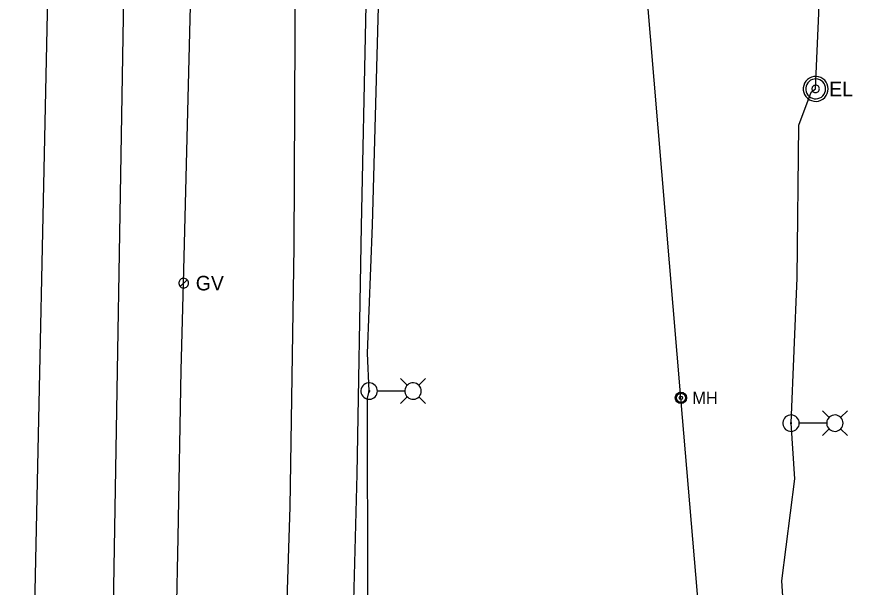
# Model space of a CAD drawing. Extents: x 600849 to 606371, y 330010 to 403088.
# Drawn here: x 604803.1 to 605024.2, y 333261.8 to 333412.8 of the extents above; entities that cross this region are included whole.
import ezdxf

# ---------------------------------------------------------------- set-up
doc = ezdxf.new("R2010")
doc.units = 0
for name, color, linetype in [('E_FTMS_Conduit', 7, 'Continuous'), ('E_LTG', 7, 'Continuous'), ('E_LTG_CID', 7, 'Continuous'), ('E_UTL_E', 7, 'Continuous'), ('E_UTL_E_UG', 7, 'Continuous'), ('E_UTL_G', 7, 'Continuous'), ('E_UTL_G_UG', 7, 'Continuous'), ('E_UTL_SAN_UG', 7, 'Continuous'), ('E_UTL_SAN_UG_MMSD', 7, 'Continuous'), ('E_UTL_W_UG', 7, 'Continuous')]:
    doc.layers.add(name, color=color, linetype=linetype)

msp = doc.modelspace()

# ---------------------------------------------------------------- linework, layer by layer
at = {"layer": 'E_FTMS_Conduit'}
msp.add_lwpolyline([(604834.27, 332793.51), (604834.27, 332793.51), (604837.8, 332828.79), (604843.62, 332859.54), (604848.45, 332908.55), (604857.59, 332953.99), (604870.57, 332999.81), (604881.56, 333070.85), (604883.3, 333104.02), (604886.34, 333150.08), (604892.01, 333248.16), (604893.18, 333291.76), (604894.37, 333357.39), (604896.64, 333466.11)], dxfattribs=at)
at = {"layer": 'E_LTG'}
for points in [[(604898.55, 333313.71), (604898.51, 333314.13), (604898.39, 333314.52), (604898.2, 333314.89), (604897.94, 333315.21), (604897.63, 333315.49), (604897.27, 333315.69), (604896.88, 333315.83), (604896.47, 333315.89), (604896.06, 333315.87), (604895.66, 333315.77), (604895.28, 333315.6), (604894.95, 333315.36), (604894.66, 333315.06), (604894.44, 333314.71), (604894.28, 333314.33), (604894.2, 333313.92), (604894.2, 333313.51), (604894.28, 333313.1), (604894.44, 333312.72), (604894.66, 333312.37), (604894.95, 333312.07), (604895.28, 333311.83), (604895.66, 333311.66), (604896.06, 333311.56), (604896.47, 333311.54), (604896.88, 333311.6), (604897.27, 333311.73), (604897.63, 333311.94), (604897.94, 333312.21), (604898.2, 333312.54), (604898.39, 333312.9), (604898.51, 333313.3), (604898.55, 333313.71)], [(604906.45, 333315.24), (604904.67, 333317.01)], [(604910.15, 333313.71), (604910.11, 333314.13), (604909.99, 333314.52), (604909.8, 333314.89), (604909.55, 333315.21), (604909.24, 333315.49), (604908.88, 333315.69), (604908.49, 333315.83), (604908.08, 333315.89), (604907.66, 333315.87), (604907.26, 333315.77), (604906.89, 333315.6), (604906.55, 333315.36), (604906.26, 333315.06), (604906.04, 333314.71), (604905.89, 333314.33), (604905.81, 333313.92), (604905.81, 333313.51), (604905.89, 333313.1), (604906.04, 333312.72), (604906.26, 333312.37), (604906.55, 333312.07), (604906.89, 333311.83), (604907.26, 333311.66), (604907.66, 333311.56), (604908.08, 333311.54), (604908.49, 333311.6), (604908.88, 333311.73), (604909.24, 333311.94), (604909.55, 333312.21), (604909.8, 333312.54), (604909.99, 333312.9), (604910.11, 333313.3), (604910.15, 333313.71)], [(604909.5, 333315.24), (604911.27, 333317.01)], [(604896.54, 333313.71), (604896.53, 333313.74), (604896.52, 333313.78), (604896.51, 333313.8), (604896.49, 333313.83), (604896.47, 333313.85), (604896.44, 333313.86), (604896.41, 333313.88), (604896.38, 333313.88), (604896.35, 333313.88), (604896.32, 333313.87), (604896.29, 333313.86), (604896.26, 333313.84), (604896.24, 333313.82), (604896.22, 333313.79), (604896.21, 333313.76), (604896.2, 333313.73), (604896.2, 333313.7), (604896.21, 333313.67), (604896.22, 333313.64), (604896.24, 333313.61), (604896.26, 333313.59), (604896.29, 333313.57), (604896.32, 333313.56), (604896.35, 333313.55), (604896.38, 333313.55), (604896.41, 333313.55), (604896.44, 333313.56), (604896.47, 333313.58), (604896.49, 333313.6), (604896.51, 333313.62), (604896.52, 333313.65), (604896.53, 333313.68), (604896.54, 333313.71)], [(604905.76, 333313.71), (604898.58, 333313.71)], [(604906.45, 333312.19), (604904.67, 333310.41)], [(604909.5, 333312.19), (604911.27, 333310.41)], [(605010.13, 333305.22), (605010.09, 333305.63), (605009.98, 333306.03), (605009.79, 333306.4), (605009.53, 333306.72), (605009.22, 333306.99), (605008.86, 333307.2), (605008.47, 333307.33), (605008.06, 333307.39), (605007.65, 333307.37), (605007.24, 333307.28), (605006.87, 333307.1), (605006.53, 333306.86), (605006.25, 333306.57), (605006.02, 333306.22), (605005.87, 333305.83), (605005.79, 333305.43), (605005.79, 333305.01), (605005.87, 333304.61), (605006.02, 333304.22), (605006.25, 333303.88), (605006.53, 333303.58), (605006.87, 333303.34), (605007.24, 333303.16), (605007.65, 333303.07), (605008.06, 333303.05), (605008.47, 333303.11), (605008.86, 333303.24), (605009.22, 333303.45), (605009.53, 333303.72), (605009.79, 333304.04), (605009.98, 333304.41), (605010.09, 333304.81), (605010.13, 333305.22)], [(605018.04, 333306.75), (605016.26, 333308.52)], [(605021.73, 333305.22), (605021.7, 333305.63), (605021.58, 333306.03), (605021.39, 333306.4), (605021.13, 333306.72), (605020.82, 333306.99), (605020.46, 333307.2), (605020.07, 333307.33), (605019.66, 333307.39), (605019.25, 333307.37), (605018.85, 333307.28), (605018.47, 333307.1), (605018.13, 333306.86), (605017.85, 333306.57), (605017.63, 333306.22), (605017.47, 333305.83), (605017.39, 333305.43), (605017.39, 333305.01), (605017.47, 333304.61), (605017.63, 333304.22), (605017.85, 333303.88), (605018.13, 333303.58), (605018.47, 333303.34), (605018.85, 333303.16), (605019.25, 333303.07), (605019.66, 333303.05), (605020.07, 333303.11), (605020.46, 333303.24), (605020.82, 333303.45), (605021.13, 333303.72), (605021.39, 333304.04), (605021.58, 333304.41), (605021.7, 333304.81), (605021.73, 333305.22)], [(605021.08, 333306.75), (605022.86, 333308.52)], [(605008.12, 333305.22), (605008.12, 333305.25), (605008.11, 333305.28), (605008.1, 333305.31), (605008.08, 333305.34), (605008.05, 333305.36), (605008.03, 333305.37), (605008, 333305.38), (605007.96, 333305.39), (605007.93, 333305.39), (605007.9, 333305.38), (605007.87, 333305.36), (605007.85, 333305.35), (605007.83, 333305.32), (605007.81, 333305.3), (605007.8, 333305.27), (605007.79, 333305.24), (605007.79, 333305.2), (605007.8, 333305.17), (605007.81, 333305.14), (605007.83, 333305.12), (605007.85, 333305.09), (605007.87, 333305.08), (605007.9, 333305.06), (605007.93, 333305.06), (605007.96, 333305.05), (605008, 333305.06), (605008.03, 333305.07), (605008.05, 333305.08), (605008.08, 333305.11), (605008.1, 333305.13), (605008.11, 333305.16), (605008.12, 333305.19), (605008.12, 333305.22)], [(605017.35, 333305.22), (605010.17, 333305.22)], [(605018.04, 333303.7), (605016.26, 333301.92)], [(605021.08, 333303.7), (605022.86, 333301.92)]]:
    msp.add_lwpolyline(points, dxfattribs=at)
at = {"layer": 'E_LTG_CID'}
for points in [[(605014.47, 333393.69), (605015.31, 333413.75), (605015.88, 333465.08), (605016.33, 333493.73), (605016.6, 333495.89), (605016.64, 333498.09), (605017.72, 333545.18), (605018.86, 333593.18), (605019.31, 333619.04), (605019.11, 333662.74), (605017.7, 333668.32), (605017.29, 333684.65), (605016.2, 333704.19), (605012.52, 333714.35), (605010.86, 333742.99), (605009.02, 333796.81), (605006.86, 333832.68), (605008.56, 333838.78), (605005.64, 333851.75), (605010.35, 333891.22), (605002.22, 333986.67)], [(604879.6, 332255.02), (604881.21, 332520.43), (604882.73, 332780.27), (604878.2, 332790.52), (604877.91, 332791.78), (604881.34, 332802.26), (604883.13, 332854.03), (604882.52, 332888.97), (604884.51, 332915.54), (604885.08, 332965.87), (604885.55, 333001.94), (604887.55, 333053.11), (604887.38, 333057.43), (604890.09, 333114.03), (604893.58, 333149.05), (604892.31, 333167.75), (604894.55, 333225.52), (604896.01, 333258.34), (604895.95, 333311.87), (604895.91, 333311.87), (604896.37, 333313.71), (604895.92, 333323.72), (604897.23, 333357.63), (604900.28, 333466.82)], [(605007.96, 333305.22), (605009.56, 333343.65), (605010.05, 333384.12), (605013.28, 333392.8), (605014.47, 333393.69)], [(605004.43, 333142.5), (605005.3, 333147), (605005.59, 333179.13), (605007.26, 333236.01), (605005.55, 333263.51), (605008.97, 333290.48), (605007.96, 333305.22)]]:
    msp.add_lwpolyline(points, dxfattribs=at)
at = {"layer": 'E_UTL_E'}
for points in [[(605017.77, 333393.69), (605017.71, 333394.32), (605017.54, 333394.92), (605017.25, 333395.48), (605016.86, 333395.97), (605016.39, 333396.38), (605015.84, 333396.7), (605015.25, 333396.9), (605014.63, 333396.99), (605014, 333396.96), (605013.39, 333396.81), (605012.82, 333396.55), (605012.31, 333396.19), (605011.88, 333395.73), (605011.54, 333395.21), (605011.31, 333394.62), (605011.19, 333394.01), (605011.19, 333393.38), (605011.31, 333392.76), (605011.54, 333392.18), (605011.88, 333391.65), (605012.31, 333391.2), (605012.82, 333390.84), (605013.39, 333390.58), (605014, 333390.43), (605014.63, 333390.4), (605015.25, 333390.49), (605015.84, 333390.69), (605016.39, 333391.01), (605016.86, 333391.42), (605017.25, 333391.91), (605017.54, 333392.47), (605017.71, 333393.07), (605017.77, 333393.69)], [(605017.77, 333393.69), (605017.71, 333394.32), (605017.54, 333394.92), (605017.25, 333395.48), (605016.86, 333395.97), (605016.39, 333396.38), (605015.84, 333396.7), (605015.25, 333396.9), (605014.63, 333396.99), (605014, 333396.96), (605013.39, 333396.81), (605012.82, 333396.55), (605012.31, 333396.19), (605011.88, 333395.73), (605011.54, 333395.21), (605011.31, 333394.62), (605011.19, 333394.01), (605011.19, 333393.38), (605011.31, 333392.76), (605011.54, 333392.18), (605011.88, 333391.65), (605012.31, 333391.2), (605012.82, 333390.84), (605013.39, 333390.58), (605014, 333390.43), (605014.63, 333390.4), (605015.25, 333390.49), (605015.84, 333390.69), (605016.39, 333391.01), (605016.86, 333391.42), (605017.25, 333391.91), (605017.54, 333392.47), (605017.71, 333393.07), (605017.77, 333393.69)], [(605017.11, 333393.69), (605017.06, 333394.19), (605016.92, 333394.68), (605016.69, 333395.12), (605016.38, 333395.52), (605016, 333395.84), (605015.57, 333396.1), (605015.09, 333396.26), (605014.6, 333396.33), (605014.1, 333396.31), (605013.61, 333396.19), (605013.15, 333395.98), (605012.74, 333395.69), (605012.4, 333395.33), (605012.13, 333394.9), (605011.94, 333394.44), (605011.84, 333393.95), (605011.84, 333393.44), (605011.94, 333392.95), (605012.13, 333392.48), (605012.4, 333392.06), (605012.74, 333391.7), (605013.15, 333391.41), (605013.61, 333391.2), (605014.1, 333391.08), (605014.6, 333391.06), (605015.09, 333391.13), (605015.57, 333391.29), (605016, 333391.54), (605016.38, 333391.87), (605016.69, 333392.27), (605016.92, 333392.71), (605017.06, 333393.19), (605017.11, 333393.69)], [(605017.11, 333393.69), (605017.06, 333394.19), (605016.92, 333394.68), (605016.69, 333395.12), (605016.38, 333395.52), (605016, 333395.84), (605015.57, 333396.1), (605015.09, 333396.26), (605014.6, 333396.33), (605014.1, 333396.31), (605013.61, 333396.19), (605013.15, 333395.98), (605012.74, 333395.69), (605012.4, 333395.33), (605012.13, 333394.9), (605011.94, 333394.44), (605011.84, 333393.95), (605011.84, 333393.44), (605011.94, 333392.95), (605012.13, 333392.48), (605012.4, 333392.06), (605012.74, 333391.7), (605013.15, 333391.41), (605013.61, 333391.2), (605014.1, 333391.08), (605014.6, 333391.06), (605015.09, 333391.13), (605015.57, 333391.29), (605016, 333391.54), (605016.38, 333391.87), (605016.69, 333392.27), (605016.92, 333392.71), (605017.06, 333393.19), (605017.11, 333393.69)], [(605015.46, 333393.69), (605015.44, 333393.88), (605015.39, 333394.06), (605015.3, 333394.23), (605015.19, 333394.38), (605015.05, 333394.5), (605014.88, 333394.59), (605014.71, 333394.66), (605014.52, 333394.68), (605014.33, 333394.67), (605014.15, 333394.63), (605013.98, 333394.55), (605013.82, 333394.44), (605013.69, 333394.31), (605013.59, 333394.15), (605013.52, 333393.97), (605013.49, 333393.79), (605013.49, 333393.6), (605013.52, 333393.42), (605013.59, 333393.24), (605013.69, 333393.08), (605013.82, 333392.95), (605013.98, 333392.84), (605014.15, 333392.76), (605014.33, 333392.71), (605014.52, 333392.71), (605014.71, 333392.73), (605014.88, 333392.79), (605015.05, 333392.89), (605015.19, 333393.01), (605015.3, 333393.16), (605015.39, 333393.33), (605015.44, 333393.51), (605015.46, 333393.69)], [(605015.46, 333393.69), (605015.44, 333393.88), (605015.39, 333394.06), (605015.3, 333394.23), (605015.19, 333394.38), (605015.05, 333394.5), (605014.88, 333394.59), (605014.71, 333394.66), (605014.52, 333394.68), (605014.33, 333394.67), (605014.15, 333394.63), (605013.98, 333394.55), (605013.82, 333394.44), (605013.69, 333394.31), (605013.59, 333394.15), (605013.52, 333393.97), (605013.49, 333393.79), (605013.49, 333393.6), (605013.52, 333393.42), (605013.59, 333393.24), (605013.69, 333393.08), (605013.82, 333392.95), (605013.98, 333392.84), (605014.15, 333392.76), (605014.33, 333392.71), (605014.52, 333392.71), (605014.71, 333392.73), (605014.88, 333392.79), (605015.05, 333392.89), (605015.19, 333393.01), (605015.3, 333393.16), (605015.39, 333393.33), (605015.44, 333393.51), (605015.46, 333393.69)]]:
    msp.add_lwpolyline(points, dxfattribs=at)
at = {"layer": 'E_UTL_E_UG'}
msp.add_lwpolyline([(604807.11, 332738.59), (604807.78, 332750.65), (604807.96, 332775.5), (604808.38, 332791.31), (604815.08, 332849.74), (604822.32, 332885.57), (604833.34, 332928.58), (604839.6, 332951.01), (604848.87, 332992.8), (604856.97, 333034.28), (604864.88, 333090.5), (604871.07, 333164.58), (604871.07, 333164.57), (604871.34, 333168.95), (604872.08, 333173.54), (604873.02, 333206.22), (604875.47, 333283.07), (604876.52, 333351.85), (604877.02, 333463.99)], dxfattribs=at)
at = {"layer": 'E_UTL_G'}
for points in [[(604848.57, 333342.28), (604848.55, 333342.53), (604848.48, 333342.76), (604848.37, 333342.98), (604848.22, 333343.17), (604848.03, 333343.33), (604847.82, 333343.45), (604847.59, 333343.53), (604847.35, 333343.57), (604847.11, 333343.55), (604846.87, 333343.5), (604846.65, 333343.39), (604846.45, 333343.25), (604846.28, 333343.08), (604846.15, 333342.87), (604846.06, 333342.64), (604846.01, 333342.41), (604846.01, 333342.16), (604846.06, 333341.92), (604846.15, 333341.7), (604846.28, 333341.49), (604846.45, 333341.31), (604846.65, 333341.17), (604846.87, 333341.07), (604847.11, 333341.01), (604847.35, 333341), (604847.59, 333341.04), (604847.82, 333341.12), (604848.03, 333341.24), (604848.22, 333341.4), (604848.37, 333341.59), (604848.48, 333341.81), (604848.55, 333342.04), (604848.57, 333342.28)], [(604846.38, 333341.38), (604848.2, 333343.19)]]:
    msp.add_lwpolyline(points, dxfattribs=at)
at = {"layer": 'E_UTL_G_UG'}
msp.add_lwpolyline([(604803.13, 333062.75), (604804.47, 333067.46), (604804.82, 333068.5), (604814.84, 333081.84), (604828.52, 333091.01), (604836.1, 333095.96), (604841.81, 333158.17), (604844.49, 333210.93), (604845.82, 333274.99), (604846.65, 333319.21), (604847.29, 333342.28), (604849.65, 333436.7), (604848.05, 333522.17), (604847.68, 333603.32), (604847.05, 333670.25), (604844.38, 333743.96), (604843.81, 333769.64), (604845.08, 333795.02)], dxfattribs=at)
at = {"layer": 'E_UTL_SAN_UG'}
for radius in [1.5, 1.2, 0.45]:
    msp.add_circle((604978.83, 333311.92), radius, dxfattribs=at)
at = {"layer": 'E_UTL_SAN_UG_MMSD'}
for points in [[(604978.83, 333311.92), (604918.55, 334029.79), (604889.58, 334663.41)], [(604992.09, 332721.29), (604983.2, 333259.95), (604978.83, 333311.92)]]:
    msp.add_lwpolyline(points, dxfattribs=at)
at = {"layer": 'E_UTL_W_UG'}
for p, q in [((604806.52, 333189.21), (604813.94, 333537.4)), ((604828.69, 333252.06), (604833.26, 333520.82))]:
    msp.add_line(p, q, dxfattribs=at)

# ---------------------------------------------------------------- texts
at = {"layer": 'E_UTL_E'}
msp.add_text('EL', height=3.849, dxfattribs=at).set_placement((605018.04, 333391.75))
msp.add_text('EL', height=3.849, dxfattribs=at).set_placement((605018.04, 333391.75))
at = {"layer": 'E_UTL_G'}
msp.add_text('GV', height=3.85, dxfattribs=at).set_placement((604850.5, 333340.36))
at = {"layer": 'E_UTL_SAN_UG'}
msp.add_text('MH', height=3.24, dxfattribs=at).set_placement((604981.83, 333310.3))

doc.saveas('drawing.dxf')
